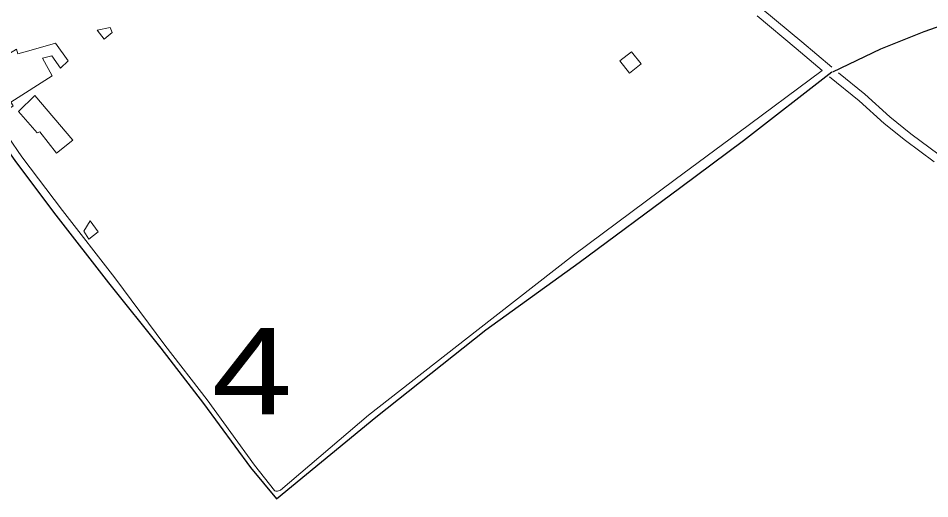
# Model space of a CAD drawing. Extents: x 476989 to 498418, y 4381813 to 4416555.
# Drawn here: x 486244 to 486771, y 4385659 to 4385937 of the extents above; entities that cross this region are included whole.
import ezdxf
from ezdxf.enums import TextEntityAlignment as Align

# ---------------------------------------------------------------- set-up
doc = ezdxf.new("R2010")
doc.units = 0
doc.header["$LTSCALE"] = 20
for name, color, linetype, lineweight in [('13', 7, 'Continuous', 13), ('36', 7, 'Continuous', 13), ('47', 7, 'Continuous', 13), ('6', 7, 'Continuous', 25)]:
    doc.layers.add(name, color=color, linetype=linetype, lineweight=lineweight)

msp = doc.modelspace()

# ---------------------------------------------------------------- linework, layer by layer
at = {"layer": '36'}
for points in [[(486544.6, 4386061.6), (486555.49, 4386051.99), (486565.36, 4386044.57), (486575.71, 4386035.06), (486585.66, 4386026.27), (486595.98, 4386018.4), (486606.16, 4386009.36), (486610.66, 4386004.2), (486616.49, 4385997.98), (486623.5, 4385989.46), (486633.36, 4385979.55), (486643.2, 4385970.03), (486651.2, 4385962.02), (486657.07, 4385957.05), (486674.26, 4385942.1), (486696.74, 4385923.39), (486714.13, 4385908.6)], [(486671.02, 4385938.29), (486693.52, 4385919.56), (486708.56, 4385906.77)], [(486142.37, 4385922.73), (486169.25, 4385920.92), (486183.49, 4385918.24), (486188.02, 4385917.05), (486195.24, 4385913.48), (486204.23, 4385908.31), (486209.48, 4385904.02), (486213.82, 4385898.89), (486218.57, 4385893.02), (486230.28, 4385879.98), (486246.4, 4385856.86), (486269.75, 4385825.93), (486300.13, 4385786.91), (486328.91, 4385748), (486353.38, 4385716.35), (486380.75, 4385678.67), (486392.21, 4385664.02)], [(486395.73, 4385664.21), (486446.64, 4385707.54), (486509.86, 4385757.05), (486564.88, 4385800.1), (486623.66, 4385843.75), (486659.91, 4385870.62), (486708.56, 4385906.77)], [(486712.77, 4385903.18), (486729.88, 4385889.29), (486744.34, 4385876.09), (486756.73, 4385866.21), (486773.27, 4385853.94)], [(486717.93, 4385905.42), (486733.14, 4385893.08), (486747.58, 4385879.89), (486759.77, 4385870.17), (486776.19, 4385857.99)], [(486392.21, 4385664.02), (486392.47, 4385663.82), (486392.98, 4385663.7), (486393.43, 4385663.66), (486393.99, 4385663.64), (486394.55, 4385663.73), (486395.2, 4385663.92), (486395.73, 4385664.21)]]:
    msp.add_lwpolyline(points, dxfattribs=at)
at = {"layer": '47'}
for points in [[(486289.92, 4385930.05), (486297.45, 4385931.59), (486298.53, 4385928.65), (486293.97, 4385924.89)], [(486265.73, 4385922.59), (486251.79, 4385918.59), (486244.03, 4385916.37), (486243.24, 4385919.16), (486232.42, 4385912.64), (486224.03, 4385908.18), (486225.24, 4385903.96), (486224.11, 4385903.38), (486225.41, 4385900.28), (486230.23, 4385901.41), (486231.25, 4385898.92), (486235.75, 4385893.61), (486231.72, 4385890.14), (486236.49, 4385882.79), (486241.42, 4385886.4), (486239.95, 4385888.52), (486263.96, 4385903.63), (486258.32, 4385913.84), (486263.67, 4385915.19), (486268.6, 4385908.14), (486273.16, 4385912.43)], [(486604.04, 4385910.54), (486597.3, 4385905.2), (486591.69, 4385912.29), (486598.43, 4385917.63)], [(486275.73, 4385866.54), (486253.81, 4385892.3), (486244.45, 4385883.13), (486255.23, 4385870.81), (486256.66, 4385871.24), (486266.32, 4385858.95)], [(486290.5, 4385813.58), (486285.12, 4385809.31), (486282.25, 4385813.92), (486285.87, 4385819.8)]]:
    msp.add_lwpolyline(points, close=True, dxfattribs=at)
at = {"layer": '6'}
for points in [[(486714.69, 4385905.9), (486742.52, 4385919.31), (486767.38, 4385929.3), (486777.82, 4385933.01)], [(486142.05, 4385918.05), (486168.65, 4385916.25), (486182.46, 4385913.66), (486186.37, 4385912.63), (486193.03, 4385909.34), (486201.55, 4385904.44), (486206.17, 4385900.66), (486210.21, 4385895.9), (486215, 4385889.97), (486226.59, 4385877.06), (486242.6, 4385854.11), (486266.03, 4385823.08), (486296.39, 4385784.07), (486326.62, 4385746.3), (486351.18, 4385714.3), (486378.4, 4385677.31), (486393.42, 4385659.22)], [(486393.35, 4385659.22), (486450.78, 4385706.33), (486514.27, 4385756.91), (486568.15, 4385795.81), (486626.88, 4385839.42), (486663.13, 4385866.29), (486714.2, 4385905.9)]]:
    msp.add_lwpolyline(points, dxfattribs=at)

# ---------------------------------------------------------------- texts
at = {"layer": '13', "width": 1.25}
msp.add_text('4', height=50, dxfattribs=at).set_placement((486379.3, 4385707.97), align=Align.CENTER)

doc.saveas('drawing.dxf')
